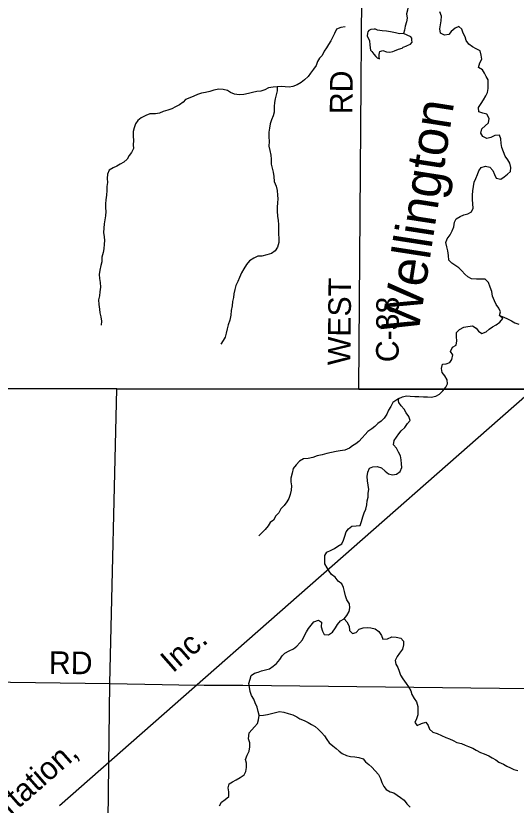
# Model space of a CAD drawing. Extents: x 1857828 to 2277390, y 930619 to 1324581.
# Drawn here: x 2051743 to 2058380, y 1160303 to 1170776 of the extents above; entities that cross this region are included whole.
import ezdxf

# ---------------------------------------------------------------- set-up
doc = ezdxf.new("R2010")
doc.units = 0
for name, color, linetype in [('GM_X_County_Road', 7, 'Continuous'), ('GM_X_County_Road_Text', 7, 'Continuous'), ('GM_X_Major_River', 7, 'Continuous'), ('GM_X_Major_River_Text', 7, 'Continuous'), ('GM_X_Minor_Lake', 7, 'Continuous'), ('GM_X_Minor_River', 7, 'Continuous'), ('GM_X_Rail_Line', 7, 'Continuous'), ('GM_X_Rail_Line_Text', 7, 'Continuous'), ('GM_X_Township', 7, 'Continuous'), ('GM_X_Township_Road', 7, 'Continuous'), ('GM_X_Township_Road_Text', 7, 'Continuous')]:
    doc.layers.add(name, color=color, linetype=linetype)

msp = doc.modelspace()

# ---------------------------------------------------------------- linework, layer by layer
at = {"layer": 'GM_X_County_Road'}
for points in [[(2056293, 1165821), (2056359, 1174522), (2056356, 1174767), (2056369, 1175348), (2056379, 1175938), (2056386, 1176574), (2056403, 1177001), (2056414, 1177716), (2056431, 1178508), (2056461, 1179546), (2056466, 1179893), (2056469, 1180421), (2056465, 1181003), (2056473, 1181448), (2056486, 1181956), (2056498, 1182433), (2056516, 1183354), (2056527, 1183865), (2056542, 1184585), (2056572, 1186217)], [(2046516, 1165826), (2051080, 1165830), (2053083, 1165829), (2056293, 1165821), (2059723, 1165822)]]:
    msp.add_lwpolyline(points, dxfattribs=at)
at = {"layer": 'GM_X_Major_River'}
for points in [[(2058209, 1168972), (2058188, 1169029), (2058179, 1169082), (2058177, 1169144), (2058158, 1169192), (2058098, 1169187), (2058042, 1169160), (2057988, 1169150), (2057935, 1169173), (2057911, 1169217), (2057926, 1169274), (2057966, 1169316), (2058011, 1169355), (2058019, 1169413), (2057988, 1169469), (2057938, 1169482), (2057883, 1169500), (2057881, 1169560), (2057914, 1169612), (2057948, 1169663), (2057977, 1169713), (2057999, 1169760), (2058010, 1169810), (2058010, 1169866), (2058007, 1169924), (2057982, 1169970), (2057958, 1170014), (2057931, 1170058), (2057881, 1170090), (2057898, 1170150), (2057926, 1170201), (2057917, 1170253), (2057900, 1170309), (2057848, 1170338), (2057799, 1170364), (2057751, 1170401), (2057718, 1170447), (2057701, 1170497), (2057675, 1170547), (2057658, 1170597), (2057619, 1170635), (2057569, 1170612), (2057518, 1170569), (2057488, 1170529), (2057430, 1170518), (2057377, 1170544), (2057368, 1170604), (2057374, 1170654), (2057383, 1170711), (2057389, 1170771), (2057368, 1170827)], [(2056821, 1165700), (2056870, 1165721), (2056925, 1165732), (2056975, 1165730), (2057035, 1165725), (2057089, 1165725), (2057150, 1165722), (2057204, 1165719), (2057254, 1165715), (2057315, 1165730), (2057362, 1165758), (2057406, 1165801), (2057446, 1165848), (2057469, 1165892), (2057463, 1165948), (2057432, 1165998), (2057399, 1166042), (2057387, 1166096), (2057400, 1166154), (2057450, 1166159), (2057500, 1166175), (2057528, 1166218), (2057538, 1166276), (2057509, 1166324), (2057536, 1166380), (2057584, 1166405), (2057592, 1166463), (2057589, 1166519), (2057590, 1166573), (2057628, 1166616), (2057684, 1166643), (2057740, 1166655), (2057799, 1166662), (2057847, 1166632), (2057880, 1166592), (2057924, 1166559), (2057980, 1166585), (2058020, 1166618), (2058064, 1166651), (2058116, 1166677), (2058164, 1166710), (2058201, 1166758), (2058159, 1166802), (2058172, 1166850), (2058150, 1166898), (2058113, 1166944), (2058090, 1166996), (2058067, 1167058), (2058055, 1167118), (2058036, 1167176), (2058011, 1167238), (2057966, 1167282), (2057912, 1167283), (2057852, 1167280), (2057785, 1167288), (2057737, 1167313), (2057698, 1167349), (2057658, 1167391), (2057621, 1167430), (2057581, 1167460), (2057526, 1167496), (2057487, 1167533), (2057483, 1167596), (2057474, 1167658), (2057461, 1167712), (2057448, 1167768), (2057466, 1167818), (2057502, 1167871), (2057531, 1167925), (2057551, 1167977), (2057560, 1168036), (2057582, 1168084), (2057637, 1168115), (2057683, 1168135), (2057740, 1168148), (2057786, 1168177), (2057807, 1168225), (2057804, 1168283), (2057798, 1168337), (2057801, 1168395), (2057805, 1168452), (2057814, 1168510), (2057823, 1168568), (2057843, 1168619), (2057866, 1168669), (2057884, 1168719), (2057916, 1168764), (2057974, 1168782), (2058028, 1168769), (2058071, 1168723), (2058092, 1168671), (2058116, 1168621), (2058175, 1168610), (2058218, 1168641), (2058262, 1168673), (2058302, 1168712), (2058308, 1168762), (2058295, 1168820), (2058268, 1168866), (2058234, 1168914), (2058209, 1168972)], [(2056753, 1165086), (2056760, 1165140), (2056794, 1165187), (2056822, 1165229), (2056853, 1165270), (2056901, 1165314), (2056939, 1165365), (2056974, 1165409), (2056954, 1165461), (2056921, 1165507), (2056896, 1165557), (2056856, 1165603), (2056821, 1165646), (2056820, 1165667), (2056819, 1165675), (2056821, 1165701)], [(2054972, 1161494), (2054972, 1161498), (2054956, 1161546), (2054943, 1161604), (2054918, 1161662), (2054898, 1161708), (2054869, 1161758), (2054850, 1161810), (2054842, 1161868), (2054835, 1161918), (2054850, 1161974), (2054864, 1162025), (2054908, 1162055), (2054956, 1162070), (2055004, 1162088), (2055056, 1162101), (2055110, 1162112), (2055156, 1162146), (2055202, 1162185), (2055245, 1162237), (2055275, 1162286), (2055313, 1162320), (2055369, 1162351), (2055425, 1162378), (2055469, 1162412), (2055512, 1162459), (2055544, 1162499), (2055571, 1162556), (2055599, 1162602), (2055625, 1162647), (2055660, 1162691), (2055698, 1162734), (2055756, 1162760), (2055797, 1162731), (2055793, 1162670), (2055810, 1162614), (2055833, 1162568), (2055891, 1162565), (2055943, 1162600), (2055982, 1162656), (2056010, 1162701), (2056050, 1162749), (2056098, 1162776), (2056133, 1162820), (2056165, 1162871), (2056172, 1162923), (2056168, 1162977), (2056135, 1163029), (2056116, 1163081), (2056104, 1163139), (2056089, 1163191), (2056068, 1163239), (2056020, 1163277), (2055981, 1163328), (2055932, 1163364), (2055899, 1163410), (2055873, 1163454), (2055842, 1163505), (2055843, 1163564), (2055843, 1163616), (2055869, 1163662), (2055925, 1163687), (2055971, 1163709), (2056016, 1163738), (2056068, 1163771), (2056088, 1163821), (2056105, 1163873), (2056125, 1163928), (2056156, 1163972), (2056202, 1164003), (2056259, 1164009), (2056309, 1164012), (2056328, 1164068), (2056344, 1164127), (2056363, 1164181), (2056385, 1164229), (2056400, 1164286), (2056404, 1164340), (2056415, 1164392), (2056417, 1164442), (2056424, 1164493), (2056415, 1164551), (2056407, 1164605), (2056404, 1164665), (2056411, 1164723), (2056433, 1164774), (2056479, 1164794), (2056535, 1164795), (2056592, 1164779), (2056640, 1164736), (2056685, 1164698), (2056737, 1164687), (2056790, 1164693), (2056841, 1164730), (2056865, 1164782), (2056860, 1164832), (2056854, 1164884), (2056845, 1164938), (2056818, 1164988), (2056790, 1165038), (2056753, 1165086)], [(2054447, 1160297), (2054473, 1160345), (2054519, 1160380), (2054570, 1160417), (2054570, 1160479), (2054559, 1160533), (2054572, 1160585), (2054616, 1160612), (2054666, 1160640), (2054720, 1160671), (2054770, 1160708), (2054796, 1160752), (2054801, 1160804), (2054801, 1160862), (2054790, 1160912), (2054811, 1160967), (2054837, 1161021), (2054846, 1161076), (2054846, 1161130), (2054831, 1161182), (2054833, 1161222), (2054840, 1161264), (2054872, 1161305), (2054910, 1161341), (2054947, 1161386), (2054963, 1161434), (2054972, 1161494)]]:
    msp.add_lwpolyline(points, dxfattribs=at)
at = {"layer": 'GM_X_Minor_Lake'}
for points in [[(2056885, 1170539), (2056833, 1170538), (2056780, 1170550), (2056712, 1170565), (2056659, 1170573), (2056601, 1170578), (2056541, 1170587), (2056512, 1170597), (2056496, 1170597), (2056454, 1170592), (2056424, 1170580), (2056412, 1170562), (2056406, 1170546), (2056405, 1170504), (2056432, 1170450), (2056440, 1170386), (2056449, 1170319), (2056463, 1170300), (2056490, 1170266), (2056516, 1170236), (2056535, 1170216), (2056565, 1170206), (2056561, 1170228), (2056562, 1170264), (2056566, 1170283), (2056570, 1170301), (2056612, 1170315)], [(2056885, 1170539), (2056833, 1170538), (2056780, 1170550), (2056712, 1170565), (2056659, 1170573), (2056601, 1170578), (2056541, 1170587), (2056512, 1170597), (2056496, 1170597), (2056454, 1170592), (2056424, 1170580), (2056412, 1170562), (2056406, 1170546), (2056405, 1170504), (2056432, 1170450), (2056440, 1170386), (2056449, 1170319), (2056463, 1170300), (2056490, 1170266), (2056516, 1170236), (2056535, 1170216), (2056565, 1170206), (2056561, 1170228), (2056562, 1170264), (2056566, 1170283), (2056570, 1170301), (2056612, 1170315)], [(2056612, 1170315), (2056660, 1170296), (2056705, 1170294), (2056745, 1170301), (2056765, 1170311), (2056819, 1170333), (2056867, 1170348), (2056881, 1170358), (2056931, 1170379), (2056935, 1170383), (2056977, 1170401), (2056999, 1170428), (2056996, 1170454), (2056994, 1170480), (2056984, 1170498), (2056885, 1170539)], [(2056612, 1170315), (2056660, 1170296), (2056705, 1170294), (2056745, 1170301), (2056765, 1170311), (2056819, 1170333), (2056867, 1170348), (2056881, 1170358), (2056931, 1170379), (2056935, 1170383), (2056977, 1170401), (2056999, 1170428), (2056996, 1170454), (2056994, 1170480), (2056984, 1170498), (2056885, 1170539)]]:
    msp.add_lwpolyline(points, dxfattribs=at)
at = {"layer": 'GM_X_Minor_River'}
for points in [[(2057042, 1171038), (2056986, 1171017), (2056950, 1170971), (2056945, 1170909), (2056938, 1170850), (2056926, 1170800), (2056933, 1170746), (2056925, 1170696), (2056908, 1170639), (2056900, 1170587), (2056885, 1170539)], [(2056112, 1170629), (2056052, 1170620), (2055998, 1170598), (2055972, 1170543), (2055949, 1170497), (2055923, 1170444), (2055892, 1170396), (2055862, 1170349), (2055832, 1170305), (2055805, 1170251), (2055769, 1170214), (2055745, 1170168), (2055726, 1170117), (2055692, 1170069), (2055653, 1170016), (2055621, 1169972), (2055573, 1169925), (2055527, 1169890), (2055473, 1169862), (2055419, 1169839), (2055367, 1169827), (2055315, 1169832), (2055265, 1169836), (2055210, 1169833), (2055158, 1169830), (2055094, 1169820), (2055044, 1169793), (2054994, 1169778), (2054940, 1169770), (2054884, 1169757), (2054828, 1169747), (2054769, 1169730), (2054705, 1169725), (2054643, 1169735), (2054590, 1169756), (2054550, 1169786), (2054493, 1169797), (2054435, 1169803), (2054371, 1169790), (2054315, 1169773), (2054261, 1169757), (2054205, 1169748), (2054152, 1169732), (2054104, 1169711), (2054050, 1169686), (2053996, 1169666), (2053961, 1169629), (2053915, 1169593), (2053863, 1169568), (2053813, 1169543), (2053761, 1169523), (2053697, 1169506), (2053647, 1169485), (2053595, 1169475), (2053522, 1169476), (2053468, 1169453), (2053404, 1169423), (2053362, 1169386), (2053331, 1169342), (2053313, 1169291), (2053300, 1169239), (2053300, 1169179), (2053305, 1169121), (2053302, 1169066), (2053306, 1169014), (2053279, 1168960), (2053245, 1168921), (2053219, 1168873), (2053178, 1168832), (2053128, 1168806), (2053082, 1168781), (2053034, 1168759), (2052980, 1168730), (2052958, 1168674), (2052957, 1168619), (2052958, 1168563), (2052952, 1168511), (2052951, 1168457), (2052947, 1168395), (2052938, 1168336), (2052935, 1168280), (2052931, 1168230), (2052936, 1168178), (2052932, 1168122), (2052925, 1168069), (2052916, 1168017), (2052910, 1167957), (2052905, 1167903), (2052917, 1167845), (2052918, 1167794), (2052915, 1167744), (2052911, 1167684), (2052900, 1167634), (2052886, 1167573), (2052883, 1167513), (2052873, 1167463), (2052858, 1167402), (2052851, 1167342), (2052855, 1167292), (2052862, 1167236), (2052867, 1167174)], [(2055210, 1169833), (2055211, 1169779), (2055198, 1169728), (2055182, 1169676), (2055175, 1169626), (2055169, 1169574), (2055170, 1169499), (2055157, 1169447), (2055135, 1169395), (2055118, 1169342), (2055106, 1169284), (2055101, 1169232), (2055101, 1169172), (2055102, 1169107), (2055099, 1169047), (2055111, 1168989), (2055124, 1168925), (2055129, 1168873), (2055132, 1168809), (2055144, 1168755), (2055155, 1168703), (2055164, 1168643), (2055170, 1168578), (2055197, 1168517), (2055210, 1168456), (2055214, 1168398), (2055217, 1168348), (2055214, 1168296), (2055208, 1168236), (2055211, 1168186), (2055214, 1168119), (2055224, 1168059), (2055229, 1168005), (2055228, 1167949), (2055228, 1167885), (2055231, 1167823), (2055232, 1167769), (2055214, 1167708), (2055185, 1167656), (2055133, 1167623), (2055071, 1167606), (2055007, 1167588), (2054952, 1167585), (2054902, 1167562), (2054844, 1167524), (2054805, 1167475), (2054767, 1167417), (2054736, 1167368), (2054708, 1167306), (2054687, 1167253), (2054663, 1167199), (2054650, 1167146), (2054636, 1167088), (2054629, 1167038), (2054619, 1166984), (2054612, 1166927), (2054601, 1166867), (2054593, 1166803), (2054580, 1166740), (2054561, 1166676), (2054547, 1166624), (2054532, 1166567), (2054518, 1166511), (2054495, 1166467), (2054463, 1166420)], [(2052867, 1167174), (2052857, 1167116), (2052852, 1167061), (2052842, 1167007), (2052843, 1166947), (2052852, 1166885), (2052856, 1166835), (2052873, 1166783), (2052882, 1166723), (2052876, 1166670)], [(2058159, 1166802), (2058215, 1166779), (2058262, 1166757), (2058316, 1166727), (2058361, 1166704), (2058413, 1166684)], [(2056822, 1165701), (2056745, 1165644), (2056717, 1165593), (2056686, 1165543), (2056662, 1165490), (2056630, 1165440), (2056587, 1165397), (2056545, 1165365), (2056507, 1165328), (2056467, 1165296), (2056413, 1165259), (2056378, 1165222), (2056338, 1165176), (2056292, 1165127), (2056252, 1165097), (2056208, 1165070), (2056169, 1165038), (2056107, 1165015), (2056044, 1165004), (2055994, 1164994), (2055932, 1164981), (2055870, 1164968), (2055806, 1164952), (2055742, 1164937), (2055682, 1164916), (2055619, 1164902), (2055559, 1164897), (2055505, 1164868), (2055462, 1164818), (2055424, 1164769), (2055407, 1164709), (2055391, 1164644), (2055392, 1164594), (2055398, 1164540), (2055397, 1164482), (2055384, 1164424), (2055364, 1164373), (2055336, 1164329), (2055301, 1164278), (2055257, 1164234), (2055230, 1164183), (2055190, 1164143), (2055160, 1164086), (2055119, 1164052), (2055089, 1164011), (2055051, 1163963), (2055005, 1163916), (2054966, 1163877)], [(2056098, 1162776), (2056132, 1162736), (2056163, 1162680), (2056170, 1162620), (2056210, 1162580), (2056258, 1162595), (2056296, 1162638), (2056350, 1162658), (2056402, 1162661), (2056453, 1162657), (2056511, 1162644), (2056560, 1162608), (2056592, 1162556), (2056613, 1162506), (2056673, 1162511), (2056729, 1162536), (2056786, 1162532), (2056848, 1162521), (2056883, 1162479), (2056885, 1162429), (2056870, 1162373), (2056834, 1162320), (2056799, 1162276), (2056773, 1162223), (2056784, 1162173), (2056808, 1162129), (2056827, 1162081), (2056846, 1162029), (2056876, 1161978), (2056919, 1161918), (2056950, 1161872), (2056981, 1161820), (2056997, 1161772), (2057026, 1161718), (2057057, 1161675), (2057073, 1161615), (2057076, 1161554), (2057075, 1161502), (2057057, 1161450), (2057036, 1161399), (2057068, 1161360), (2057122, 1161388), (2057180, 1161407), (2057213, 1161363), (2057229, 1161313), (2057274, 1161272), (2057331, 1161256), (2057387, 1161227), (2057446, 1161203), (2057496, 1161182), (2057545, 1161162), (2057591, 1161136), (2057652, 1161121), (2057702, 1161102), (2057749, 1161082), (2057803, 1161060), (2057850, 1161035), (2057904, 1161003), (2057953, 1160986), (2058015, 1160960), (2058062, 1160931), (2058108, 1160907), (2058151, 1160873), (2058209, 1160846), (2058256, 1160820), (2058304, 1160801), (2058349, 1160777), (2058401, 1160762)], [(2054972, 1161494), (2055029, 1161497), (2055083, 1161507), (2055135, 1161522), (2055189, 1161535), (2055241, 1161545), (2055299, 1161538), (2055356, 1161518), (2055416, 1161501), (2055469, 1161475), (2055511, 1161448), (2055566, 1161428), (2055619, 1161401), (2055665, 1161373), (2055712, 1161349), (2055752, 1161314), (2055799, 1161268), (2055836, 1161224), (2055868, 1161173), (2055901, 1161131), (2055950, 1161089), (2055992, 1161056), (2056031, 1161020), (2056071, 1160988), (2056130, 1160963), (2056182, 1160949), (2056241, 1160944), (2056293, 1160938), (2056348, 1160917), (2056382, 1160879), (2056425, 1160845), (2056463, 1160810), (2056510, 1160760), (2056553, 1160710), (2056578, 1160656), (2056598, 1160606), (2056623, 1160551), (2056656, 1160511), (2056708, 1160479), (2056759, 1160468), (2056799, 1160436), (2056844, 1160406), (2056892, 1160369), (2056929, 1160321), (2056972, 1160279)]]:
    msp.add_lwpolyline(points, dxfattribs=at)
at = {"layer": 'GM_X_Rail_Line'}
msp.add_lwpolyline([(2052322, 1160299), (2053419, 1161265), (2058169, 1165436), (2061355, 1168238), (2062639, 1169362), (2064657, 1171134), (2067321, 1173471), (2069915, 1175749), (2072264, 1177811), (2074107, 1179425), (2075287, 1180462), (2076995, 1181961), (2078402, 1183202), (2079029, 1183752), (2080546, 1185083), (2081757, 1186146), (2082928, 1187175), (2083763, 1187908), (2085541, 1189467), (2086816, 1190588), (2087842, 1191487), (2088257, 1191851), (2088439, 1192008)], dxfattribs=at)
at = {"layer": 'GM_X_Township'}
msp.add_lwpolyline([(2032206, 1165870), (2032243, 1167507), (2032281, 1179371), (2032309, 1188668), (2032348, 1192998), (2035009, 1192996), (2046211, 1193046), (2052905, 1193059), (2052996, 1193078), (2056703, 1193080), (2060043, 1193100), (2060012, 1189567), (2060011, 1189355), (2059891, 1179593), (2059723, 1165822), (2056293, 1165821), (2053083, 1165829), (2051080, 1165830), (2046516, 1165826), (2039516, 1165835), (2032339, 1165871)], close=True, dxfattribs=at)
msp.add_lwpolyline([(2032187, 1160189), (2032191, 1160394), (2032191, 1160469), (2032202, 1162261), (2032206, 1165870), (2032339, 1165871), (2039516, 1165835), (2046516, 1165826), (2051080, 1165830), (2053083, 1165829), (2056293, 1165821), (2059723, 1165822), (2059673, 1162156), (2059668, 1161839), (2059568, 1154416)], dxfattribs=at)
at = {"layer": 'GM_X_Township_Road'}
for points in [[(2052992, 1161916), (2053083, 1165829)], [(2046410, 1162005), (2052992, 1161916)], [(2052789, 1146775), (2052896, 1150468), (2052896, 1154306), (2052992, 1161916)], [(2052992, 1161916), (2053686, 1161904), (2053907, 1161901), (2054242, 1161898), (2054753, 1161894), (2059668, 1161839)]]:
    msp.add_lwpolyline(points, dxfattribs=at)

# ---------------------------------------------------------------- texts
at = {"layer": 'GM_X_County_Road_Text'}
for s, rotation, p in [('RD', 89.5063, (2056207, 1169469)), ('WEST', 89.4945, (2056181, 1166139)), ('C-38', 89.6558, (2056820, 1166179))]:
    msp.add_text(s, height=300, rotation=rotation, dxfattribs=at).set_placement(p)
at = {"layer": 'GM_X_Major_River_Text'}
msp.add_text('Wellington', height=500.2, rotation=81.1622, dxfattribs=at).set_placement((2057078, 1166538))
at = {"layer": 'GM_X_Rail_Line_Text'}
for s, rotation, p in [('Inc.', 41.1853, (2053826, 1162049)), ('Transportation,', 41.2571, (2050572, 1159196))]:
    msp.add_text(s, height=299, rotation=rotation, dxfattribs=at).set_placement(p)
at = {"layer": 'GM_X_Township_Road_Text'}
msp.add_text('RD', height=300, rotation=359.5063, dxfattribs=at).set_placement((2052181, 1162045))

doc.saveas('drawing.dxf')
